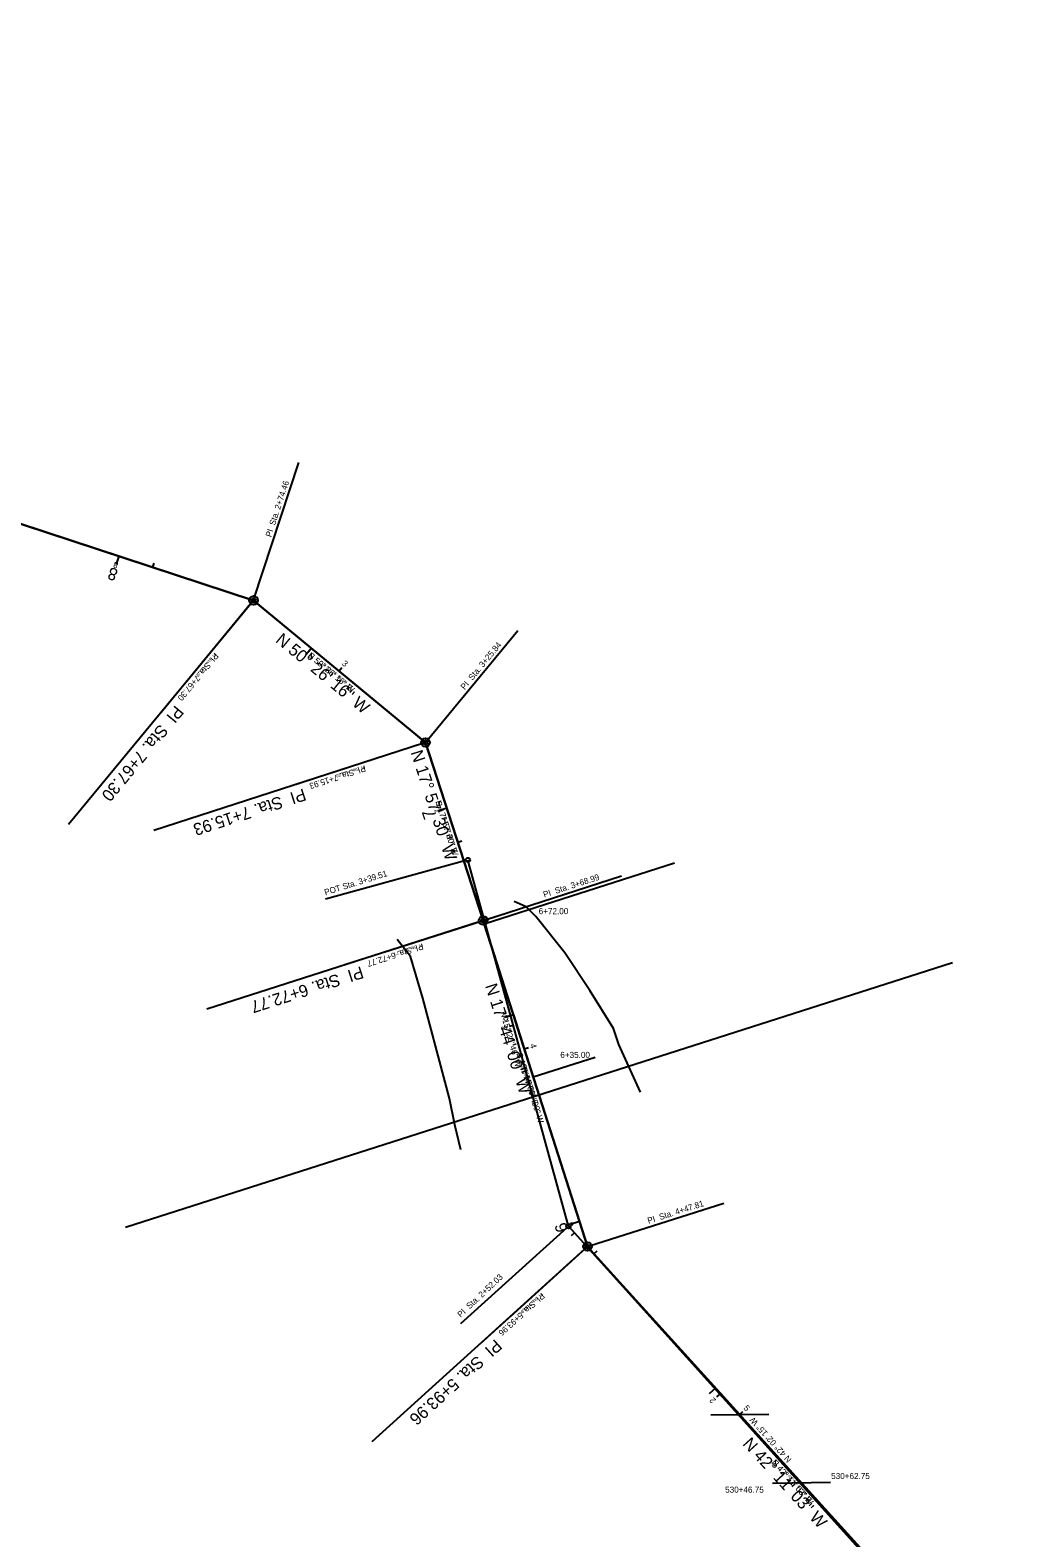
# Model space of a CAD drawing. Extents: x 2261207 to 2264340, y 653057 to 655601.
# Drawn here: x 2261437.3 to 2261667.5, y 655228.6 to 655575.8 of the extents above; entities that cross this region are included whole.
import ezdxf

# ---------------------------------------------------------------- set-up
doc = ezdxf.new("R2010")
doc.units = 0
for name, color, linetype in [('CL_X_Construction', 7, 'Continuous'), ('Default', 7, 'Continuous'), ('DT_P_Tie', 7, 'Continuous'), ('DT_X_Triangles', 7, 'Continuous'), ('GE_X_CL_10', 7, 'Continuous'), ('GE_X_CL_20', 7, 'Continuous'), ('GE_X_CL_5', 7, 'Continuous'), ('GK_Patterns', 7, 'Continuous'), ('SC_Scratch1', 7, 'Continuous'), ('SC_Scratch10', 7, 'Continuous'), ('SC_Scratch2', 7, 'Continuous'), ('SC_Scratch5', 7, 'Continuous')]:
    doc.layers.add(name, color=color, linetype=linetype)

msp = doc.modelspace()

# ---------------------------------------------------------------- linework, layer by layer
at = {"layer": 'CL_X_Construction'}
for p, q in [((2261488.74, 655444.51), (2261337.92, 655494.06)), ((2261488.74, 655444.51), (2261337.92, 655494.06)), ((2261528.34, 655411.79), (2261488.74, 655444.51)), ((2261528.34, 655411.79), (2261488.74, 655444.51)), ((2261541.65, 655370.74), (2261528.34, 655411.79)), ((2261541.65, 655370.74), (2261528.34, 655411.79)), ((2261565.65, 655295.67), (2261541.65, 655370.74)), ((2261565.65, 655295.67), (2261541.65, 655370.74)), ((2261663.66, 655187.52), (2261565.65, 655295.67)), ((2261663.66, 655187.52), (2261565.65, 655295.67))]:
    msp.add_line(p, q, dxfattribs=at)
at = {"layer": 'Default'}
for p, q in [((2261546.9, 655372.38), (2261536.4, 655369.09)), ((2261594.05, 655256.92), (2261607.41, 655257.11)), ((2261608.3, 655241.2), (2261621.64, 655241.38))]:
    msp.add_line(p, q, dxfattribs=at)
msp.add_lwpolyline([(2261600.73, 655257.02), (2261565.65, 655295.67), (2261541.65, 655370.74), (2261528.34, 655411.79), (2261488.74, 655444.51), (2261337.92, 655494.06), (2261256.04, 655575.83), (2261256.04, 655575.83)], dxfattribs=at)
at = {"layer": 'DT_P_Tie'}
for points in [[(2261577.88, 655331.21), (2261572.88, 655342.2), (2261571.62, 655345.91), (2261566.17, 655354.67), (2261560.43, 655363.34), (2261553.72, 655371.69), (2261551.56, 655373.95), (2261548.79, 655375.17)], [(2261536.49, 655317.97), (2261535.12, 655323.75), (2261533.9, 655329.74), (2261532.89, 655333.53), (2261527.7, 655352.87), (2261524.85, 655362.46), (2261521.77, 655366.41)]]:
    msp.add_lwpolyline(points, dxfattribs=at)
at = {"layer": 'DT_X_Triangles'}
for p, q in [((2261541.65, 655370.74), (2261541.03, 655372.66)), ((2261556.48, 655324.36), (2261541.65, 655370.74))]:
    msp.add_line(p, q, dxfattribs=at)
at = {"layer": 'GE_X_CL_10'}
for p, q in [((2261488.74, 655444.51), (2261337.92, 655494.06)), ((2261457.67, 655454.72), (2261457.36, 655453.77)), ((2261488.42, 655444.13), (2261467.42, 655418.71)), ((2261528.34, 655411.79), (2261488.74, 655444.51)), ((2261502.08, 655433.49), (2261501.44, 655432.72)), ((2261527.87, 655411.64), (2261497.06, 655401.65)), ((2261541.65, 655370.74), (2261528.34, 655411.79)), ((2261533.25, 655396.64), (2261532.3, 655396.33)), ((2261541.17, 655370.58), (2261509.79, 655360.55)), ((2261565.65, 655295.67), (2261541.65, 655370.74)), ((2261548.59, 655349.05), (2261547.63, 655348.74)), ((2261563.81, 655301.42), (2261562.86, 655301.12)), ((2261565.28, 655295.33), (2261540.83, 655273.17)), ((2261663.66, 655187.52), (2261565.65, 655295.67)), ((2261595.17, 655263.1), (2261594.43, 655262.43))]:
    msp.add_line(p, q, dxfattribs=at)
for centre in [(2261488.74, 655444.51), (2261528.34, 655411.79), (2261541.65, 655370.74), (2261565.65, 655295.67)]:
    msp.add_circle(centre, 0.5, dxfattribs=at)
at = {"layer": 'GE_X_CL_20'}
for p, q in [((2261488.74, 655444.51), (2261337.92, 655494.06)), ((2261488.74, 655444.51), (2261337.92, 655494.06)), ((2261457.67, 655454.72), (2261457.05, 655452.82)), ((2261457.67, 655454.72), (2261457.05, 655452.82)), ((2261457.67, 655454.72), (2261457.05, 655452.82)), ((2261457.67, 655454.72), (2261457.05, 655452.82)), ((2261528.34, 655411.79), (2261488.74, 655444.51)), ((2261528.34, 655411.79), (2261488.74, 655444.51)), ((2261488.1, 655443.74), (2261446.11, 655392.91)), ((2261488.1, 655443.74), (2261446.11, 655392.91)), ((2261488.1, 655443.74), (2261446.11, 655392.91)), ((2261488.1, 655443.74), (2261446.11, 655392.91)), ((2261502.08, 655433.49), (2261500.8, 655431.95)), ((2261502.08, 655433.49), (2261500.8, 655431.95)), ((2261502.08, 655433.49), (2261500.8, 655431.95)), ((2261502.08, 655433.49), (2261500.8, 655431.95)), ((2261527.39, 655411.48), (2261465.78, 655391.52)), ((2261527.39, 655411.48), (2261465.78, 655391.52)), ((2261527.39, 655411.48), (2261465.78, 655391.52)), ((2261527.39, 655411.48), (2261465.78, 655391.52)), ((2261541.65, 655370.74), (2261528.34, 655411.79)), ((2261541.65, 655370.74), (2261528.34, 655411.79)), ((2261533.25, 655396.64), (2261531.35, 655396.02)), ((2261533.25, 655396.64), (2261531.35, 655396.02)), ((2261533.25, 655396.64), (2261531.35, 655396.02)), ((2261533.25, 655396.64), (2261531.35, 655396.02)), ((2261540.7, 655370.43), (2261477.94, 655350.36)), ((2261540.7, 655370.43), (2261477.94, 655350.36)), ((2261540.7, 655370.43), (2261477.94, 655350.36)), ((2261540.7, 655370.43), (2261477.94, 655350.36)), ((2261565.65, 655295.67), (2261541.65, 655370.74)), ((2261565.65, 655295.67), (2261541.65, 655370.74)), ((2261548.59, 655349.05), (2261546.68, 655348.44)), ((2261548.59, 655349.05), (2261546.68, 655348.44)), ((2261548.59, 655349.05), (2261546.68, 655348.44)), ((2261548.59, 655349.05), (2261546.68, 655348.44)), ((2261563.81, 655301.42), (2261561.91, 655300.82)), ((2261563.81, 655301.42), (2261561.91, 655300.82)), ((2261563.81, 655301.42), (2261561.91, 655300.82)), ((2261563.81, 655301.42), (2261561.91, 655300.82)), ((2261564.91, 655295), (2261516.01, 655250.68)), ((2261564.91, 655295), (2261516.01, 655250.68)), ((2261564.91, 655295), (2261516.01, 655250.68)), ((2261564.91, 655295), (2261516.01, 655250.68)), ((2261663.66, 655187.52), (2261565.65, 655295.67)), ((2261663.66, 655187.52), (2261565.65, 655295.67)), ((2261595.17, 655263.1), (2261593.69, 655261.75)), ((2261595.17, 655263.1), (2261593.69, 655261.75)), ((2261595.17, 655263.1), (2261593.69, 655261.75)), ((2261595.17, 655263.1), (2261593.69, 655261.75))]:
    msp.add_line(p, q, dxfattribs=at)
for centre in [(2261488.74, 655444.51), (2261488.74, 655444.51), (2261488.74, 655444.51), (2261488.74, 655444.51), (2261528.34, 655411.79), (2261528.34, 655411.79), (2261528.34, 655411.79), (2261528.34, 655411.79), (2261541.65, 655370.74), (2261541.65, 655370.74), (2261541.65, 655370.74), (2261541.65, 655370.74), (2261565.65, 655295.67), (2261565.65, 655295.67), (2261565.65, 655295.67), (2261565.65, 655295.67)]:
    msp.add_circle(centre, 1, dxfattribs=at)
at = {"layer": 'GE_X_CL_5'}
for p, q in [((2261488.74, 655444.51), (2261337.92, 655494.06)), ((2261457.67, 655454.72), (2261457.36, 655453.77)), ((2261488.42, 655444.13), (2261473.25, 655425.76)), ((2261528.34, 655411.79), (2261488.74, 655444.51)), ((2261502.08, 655433.49), (2261501.44, 655432.72)), ((2261527.87, 655411.64), (2261505.34, 655404.34)), ((2261541.65, 655370.74), (2261528.34, 655411.79)), ((2261533.25, 655396.64), (2261532.3, 655396.33)), ((2261541.17, 655370.58), (2261518.73, 655363.41)), ((2261565.65, 655295.67), (2261541.65, 655370.74)), ((2261548.59, 655349.05), (2261547.63, 655348.74)), ((2261563.81, 655301.42), (2261562.86, 655301.12)), ((2261565.28, 655295.33), (2261547.84, 655279.52)), ((2261663.66, 655187.52), (2261565.65, 655295.67)), ((2261595.17, 655263.1), (2261594.43, 655262.43))]:
    msp.add_line(p, q, dxfattribs=at)
for centre in [(2261488.74, 655444.51), (2261528.34, 655411.79), (2261541.65, 655370.74), (2261565.65, 655295.67)]:
    msp.add_circle(centre, 0.25, dxfattribs=at)
at = {"layer": 'GK_Patterns'}
msp.add_lwpolyline([(2261459.23, 655300.15), (2261649.73, 655361.07)], dxfattribs=at)
at = {"layer": 'SC_Scratch1'}
for p, q in [((2261337.92, 655494.06), (2261488.74, 655444.51)), ((2261488.74, 655444.51), (2261528.34, 655411.79)), ((2261528.34, 655411.79), (2261541.65, 655370.74)), ((2261541.65, 655370.74), (2261565.65, 655295.67)), ((2261565.65, 655295.67), (2261663.66, 655187.52))]:
    msp.add_line(p, q, dxfattribs=at)
for points in [[(2261548.59, 655349.05), (2261541.88, 655370), (2261585.73, 655384.03)], [(2261548.59, 655349.05), (2261553.15, 655334.76), (2261567.44, 655339.33)]]:
    msp.add_lwpolyline(points, dxfattribs=at)
at = {"layer": 'SC_Scratch10'}
for p, q in [((2261337.92, 655494.06), (2261488.74, 655444.51)), ((2261488.74, 655444.51), (2261528.34, 655411.79)), ((2261541.65, 655370.74), (2261528.34, 655411.79)), ((2261528.34, 655411.79), (2261541.65, 655370.74)), ((2261541.65, 655370.74), (2261565.65, 655295.67)), ((2261565.65, 655295.67), (2261663.66, 655187.52))]:
    msp.add_line(p, q, dxfattribs=at)
at = {"layer": 'SC_Scratch2'}
for p, q in [((2261337.92, 655494.06), (2261488.74, 655444.51)), ((2261488.89, 655444.99), (2261499.17, 655476.26)), ((2261488.89, 655444.99), (2261499.17, 655476.26)), ((2261465.5, 655452.15), (2261465.81, 655453.1)), ((2261465.5, 655452.15), (2261465.81, 655453.1)), ((2261488.74, 655444.51), (2261528.34, 655411.79)), ((2261528.66, 655412.18), (2261549.61, 655437.53)), ((2261528.66, 655412.18), (2261549.61, 655437.53)), ((2261508.43, 655428.25), (2261509.06, 655429.02)), ((2261508.43, 655428.25), (2261509.06, 655429.02)), ((2261528.34, 655411.79), (2261541.65, 655370.74)), ((2261535.79, 655388.81), (2261536.74, 655389.11)), ((2261535.79, 655388.81), (2261536.74, 655389.11)), ((2261542.13, 655370.89), (2261573.5, 655381.06)), ((2261542.13, 655370.89), (2261573.5, 655381.06)), ((2261541.65, 655370.74), (2261565.65, 655295.67)), ((2261551.09, 655341.2), (2261552.05, 655341.51)), ((2261551.09, 655341.2), (2261552.05, 655341.51)), ((2261566.13, 655295.82), (2261597.03, 655305.7)), ((2261566.13, 655295.82), (2261597.03, 655305.7)), ((2261565.65, 655295.67), (2261663.66, 655187.52)), ((2261567.13, 655294.04), (2261567.87, 655294.72)), ((2261567.13, 655294.04), (2261567.87, 655294.72)), ((2261600.7, 655256.99), (2261601.44, 655257.67)), ((2261600.7, 655256.99), (2261601.44, 655257.67))]:
    msp.add_line(p, q, dxfattribs=at)
for centre in [(2261488.74, 655444.51), (2261488.74, 655444.51), (2261528.34, 655411.79), (2261528.34, 655411.79), (2261541.65, 655370.74), (2261541.65, 655370.74), (2261565.65, 655295.67), (2261565.65, 655295.67)]:
    msp.add_circle(centre, 0.5, dxfattribs=at)
at = {"layer": 'SC_Scratch5'}
for p, q in [((2261537.63, 655384.58), (2261505.28, 655375.7)), ((2261537.63, 655384.58), (2261505.28, 655375.7)), ((2261537.63, 655384.58), (2261505.28, 655375.7)), ((2261561.27, 655300.36), (2261538.12, 655384.71)), ((2261548.57, 655346.62), (2261547.61, 655346.35)), ((2261548.57, 655346.62), (2261547.61, 655346.35)), ((2261548.57, 655346.62), (2261547.61, 655346.35)), ((2261560.9, 655300.02), (2261536.37, 655277.91)), ((2261560.9, 655300.02), (2261536.37, 655277.91)), ((2261560.9, 655300.02), (2261536.37, 655277.91)), ((2261667.55, 655182.48), (2261561.27, 655300.36)), ((2261562.62, 655298.85), (2261561.88, 655298.18)), ((2261562.62, 655298.85), (2261561.88, 655298.18)), ((2261562.62, 655298.85), (2261561.88, 655298.18)), ((2261596.11, 655261.71), (2261595.36, 655261.05)), ((2261596.11, 655261.71), (2261595.36, 655261.05)), ((2261596.11, 655261.71), (2261595.36, 655261.05))]:
    msp.add_line(p, q, dxfattribs=at)
for centre in [(2261538.12, 655384.71), (2261538.12, 655384.71), (2261538.12, 655384.71), (2261561.27, 655300.36), (2261561.27, 655300.36), (2261561.27, 655300.36)]:
    msp.add_circle(centre, 0.5, dxfattribs=at)

# ---------------------------------------------------------------- texts
at = {"layer": 'Default'}
for s, p in [('6+72.00', (2261554.41, 655372.23)), ('6+35.00', (2261559.39, 655339.12)), ('530+62.75', (2261621.78, 655242.13)), ('530+46.75', (2261597.36, 655238.99))]:
    msp.add_text(s, height=1.4, rotation=0.0003, dxfattribs=at).set_placement(p)
at = {"layer": 'GE_X_CL_10'}
for s, rotation, p in [('8', 161.8126, (2261457.69, 655453.14)), ('PI  Sta. 7+67.30', 230.4377, (2261479.72, 655432.5)), ('N 50%%d 26\' 16" W', 320.4377, (2261501.08, 655431.59)), ('PI  Sta. 7+15.93', 197.9583, (2261514.29, 655406.5)), ('7', 107.9583, (2261532, 655395.64)), ('N 17%%d 57\' 30" W', 287.9583, (2261530.56, 655398.16)), ('PI  Sta. 6+72.77', 197.7332, (2261527.58, 655365.5)), ('N 17%%d 44\' 00" W', 287.7332, (2261550.32, 655336.57)), ('6', 107.7332, (2261562.55, 655300.45)), ('PI  Sta. 5+93.96', 222.1843, (2261555.01, 655285.08)), ('N 42%%d 11\' 03" W', 312.1843, (2261607.95, 655245.87))]:
    msp.add_text(s, height=1.4, rotation=rotation, dxfattribs=at).set_placement(p)
at = {"layer": 'GE_X_CL_20'}
for s, rotation, p in [('8', 161.8126, (2261457.7, 655451.55)), ('8', 161.8126, (2261457.7, 655451.55)), ('8', 161.8126, (2261457.7, 655451.55)), ('8', 161.8126, (2261457.7, 655451.55)), ('N 50%%d 26\' 16" W', 320.4377, (2261493.61, 655435.04)), ('N 50%%d 26\' 16" W', 320.4377, (2261493.61, 655435.04)), ('PI  Sta. 7+67.30', 230.4377, (2261470.71, 655420.49)), ('PI  Sta. 7+67.30', 230.4377, (2261470.71, 655420.49)), ('PI  Sta. 7+67.30', 230.4377, (2261470.71, 655420.49)), ('PI  Sta. 7+67.30', 230.4377, (2261470.71, 655420.49)), ('N 17%%d 57\' 30" W', 287.9583, (2261524.88, 655409.49)), ('N 17%%d 57\' 30" W', 287.9583, (2261524.88, 655409.49)), ('PI  Sta. 7+15.93', 197.9583, (2261500.24, 655401.21)), ('PI  Sta. 7+15.93', 197.9583, (2261500.24, 655401.21)), ('PI  Sta. 7+15.93', 197.9583, (2261500.24, 655401.21)), ('PI  Sta. 7+15.93', 197.9583, (2261500.24, 655401.21)), ('7', 107.9583, (2261530.75, 655394.64)), ('7', 107.9583, (2261530.75, 655394.64)), ('7', 107.9583, (2261530.75, 655394.64)), ('7', 107.9583, (2261530.75, 655394.64)), ('PI  Sta. 6+72.77', 197.7332, (2261513.5, 655360.27)), ('PI  Sta. 6+72.77', 197.7332, (2261513.5, 655360.27)), ('PI  Sta. 6+72.77', 197.7332, (2261513.5, 655360.27)), ('PI  Sta. 6+72.77', 197.7332, (2261513.5, 655360.27)), ('N 17%%d 44\' 00" W', 287.7332, (2261542.03, 655355.75)), ('N 17%%d 44\' 00" W', 287.7332, (2261542.03, 655355.75)), ('6', 107.7332, (2261561.29, 655299.48)), ('6', 107.7332, (2261561.29, 655299.48)), ('6', 107.7332, (2261561.29, 655299.48)), ('6', 107.7332, (2261561.29, 655299.48)), ('PI  Sta. 5+93.96', 222.1843, (2261544.37, 655274.49)), ('PI  Sta. 5+93.96', 222.1843, (2261544.37, 655274.49)), ('PI  Sta. 5+93.96', 222.1843, (2261544.37, 655274.49)), ('PI  Sta. 5+93.96', 222.1843, (2261544.37, 655274.49)), ('N 42%%d 11\' 03" W', 312.1843, (2261601.25, 655250.14)), ('N 42%%d 11\' 03" W', 312.1843, (2261601.25, 655250.14))]:
    msp.add_text(s, height=2.8, rotation=rotation, dxfattribs=at).set_placement(p)
at = {"layer": 'GE_X_CL_5'}
for s, rotation, p in [('8', 161.8126, (2261457.42, 655453.22)), ('PI  Sta. 7+67.30', 230.4377, (2261479.72, 655432.5)), ('N 50%%d 26\' 16" W', 320.4377, (2261504.63, 655429.57)), ('PI  Sta. 7+15.93', 197.9583, (2261514.29, 655406.5)), ('7', 107.9583, (2261531.89, 655396)), ('N 17%%d 57\' 30" W', 287.9583, (2261532.46, 655394.55)), ('PI  Sta. 6+72.77', 197.7332, (2261527.58, 655365.5)), ('N 17%%d 44\' 00" W', 287.7332, (2261551.12, 655336.54)), ('6', 107.7332, (2261562.46, 655300.73)), ('PI  Sta. 5+93.96', 222.1843, (2261555.01, 655285.08)), ('N 42%%d 11\' 03" W', 312.1843, (2261611.08, 655243.46))]:
    msp.add_text(s, height=0.7, rotation=rotation, dxfattribs=at).set_placement(p)
at = {"layer": 'SC_Scratch2'}
for s, rotation, p in [('PI  Sta. 2+74.46', 71.8126, (2261492.76, 655458.98)), ('PI  Sta. 2+74.46', 71.8126, (2261492.76, 655458.98)), ('PI  Sta. 3+25.84', 50.4377, (2261537.36, 655423.8)), ('PI  Sta. 3+25.84', 50.4377, (2261537.36, 655423.8)), ('S 50%%d 26\' 16" E', 320.4377, (2261501.17, 655431.51)), ('3', 320.4377, (2261508.96, 655429.75)), ('3', 320.4377, (2261508.96, 655429.75)), ('S 17%%d 57\' 30" E', 287.9583, (2261530.59, 655398.03)), ('PI  Sta. 3+68.99', 17.9583, (2261555.7, 655376.03)), ('PI  Sta. 3+68.99', 17.9583, (2261555.7, 655376.03)), ('S 17%%d 44\' 00" E', 287.7332, (2261549.25, 655340.06)), ('4', 287.7332, (2261552.36, 655342.15)), ('4', 287.7332, (2261552.36, 655342.15)), ('PI  Sta. 4+47.81', 17.7332, (2261579.73, 655300.91)), ('PI  Sta. 4+47.81', 17.7332, (2261579.73, 655300.91)), ('5', 312.1843, (2261601.46, 655258.4)), ('5', 312.1843, (2261601.46, 655258.4)), ('S 42%%d 11\' 03" E', 312.1843, (2261608.04, 655245.77))]:
    msp.add_text(s, height=1.4, rotation=rotation, dxfattribs=at).set_placement(p)
at = {"layer": 'SC_Scratch5'}
for s, rotation, p in [('POT Sta. 3+39.51', 17.2755, (2261505.28, 655376.55)), ('N 15%%d 20\' 46" W', 285.3462, (2261545.56, 655349.64)), ('3', 105.3462, (2261547.27, 655345.7)), ('3', 105.3462, (2261547.27, 655345.7)), ('3', 105.3462, (2261547.27, 655345.7)), ('PI  Sta. 2+52.03', 43.1345, (2261536.45, 655279.26)), ('2', 132.0375, (2261595.34, 655260.32)), ('2', 132.0375, (2261595.34, 655260.32)), ('2', 132.0375, (2261595.34, 655260.32)), ('N 42%%d 02\' 15" W', 132.0375, (2261612.76, 655246.7))]:
    msp.add_text(s, height=1.4, rotation=rotation, dxfattribs=at).set_placement(p)

doc.saveas('drawing.dxf')
